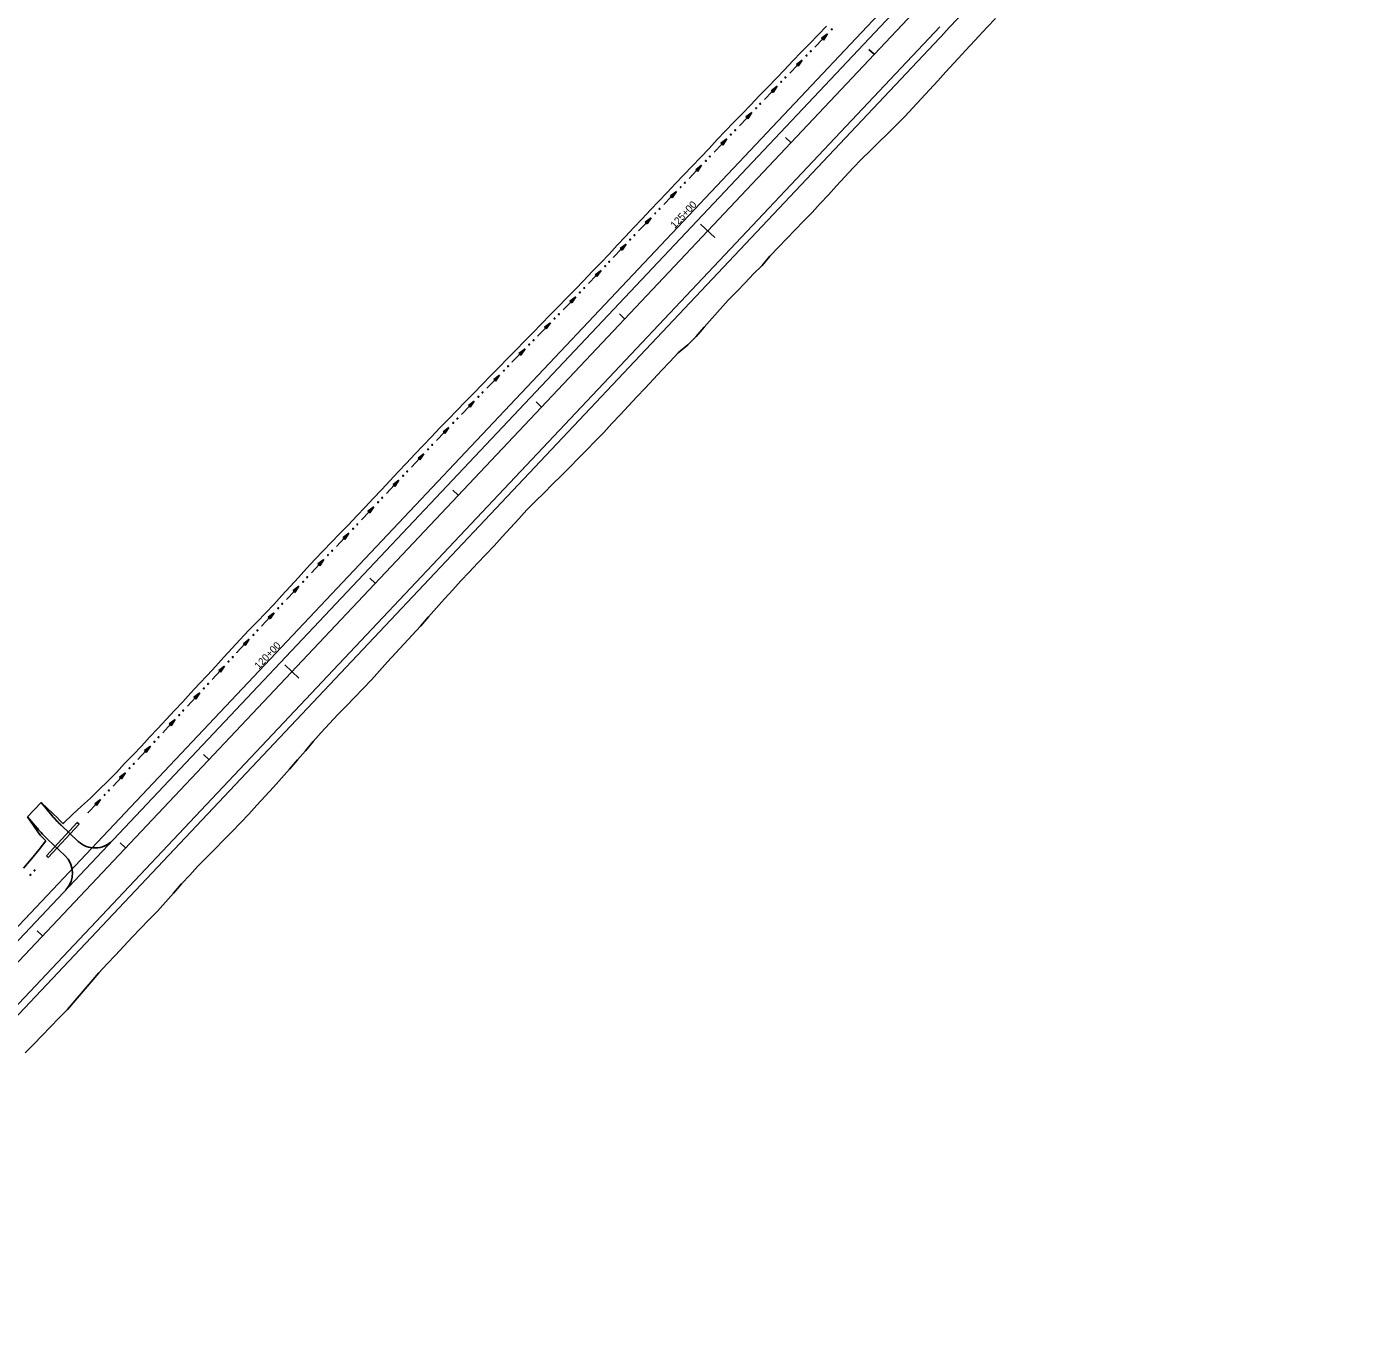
# Model space of a CAD drawing. Extents: x 1375694 to 1433473, y 1931050 to 1967991.
# Drawn here: x 1376795 to 1377906, y 1931932 to 1933018 of the extents above; entities that cross this region are included whole.
import ezdxf

# ---------------------------------------------------------------- set-up
doc = ezdxf.new("R2010")
doc.units = 0
for name, color, linetype in [('62', 7, 'Continuous'), ('R_Drainage', 7, 'Continuous'), ('R_Horz Alg', 7, 'Continuous'), ('R_Horz Alg Annot', 7, 'Continuous'), ('R_Proposed Const Limits', 7, 'Continuous'), ('R_Proposed Road', 7, 'Continuous')]:
    doc.layers.add(name, color=color, linetype=linetype)

msp = doc.modelspace()

# ---------------------------------------------------------------- linework, layer by layer
at = {"layer": '62'}
for p, q in [((1377456, 1933012), (1377451.1, 1933008.4)), ((1377452.7, 1933006.9), (1377456, 1933012)), ((1377451.1, 1933008.4), (1377452.7, 1933006.9)), ((1377435.2, 1932990.4), (1377430.3, 1932986.8)), ((1377431.8, 1932985.3), (1377435.2, 1932990.4)), ((1377430.3, 1932986.8), (1377431.8, 1932985.3)), ((1377414.4, 1932968.7), (1377409.5, 1932965.1)), ((1377409.5, 1932965.1), (1377411, 1932963.7)), ((1377411, 1932963.7), (1377414.4, 1932968.7)), ((1377393.6, 1932947), (1377388.7, 1932943.4)), ((1377388.7, 1932943.4), (1377390.3, 1932941.9)), ((1377390.3, 1932941.9), (1377393.6, 1932947)), ((1377372.9, 1932925.3), (1377368, 1932921.7)), ((1377368, 1932921.7), (1377369.5, 1932920.2)), ((1377369.5, 1932920.2), (1377372.9, 1932925.3)), ((1377352.1, 1932903.6), (1377347.2, 1932899.9)), ((1377347.2, 1932899.9), (1377348.8, 1932898.5)), ((1377348.8, 1932898.5), (1377352.1, 1932903.6)), ((1377331.3, 1932881.9), (1377326.4, 1932878.3)), ((1377326.4, 1932878.3), (1377327.9, 1932876.8)), ((1377327.9, 1932876.8), (1377331.3, 1932881.9)), ((1377310.5, 1932860.3), (1377305.5, 1932856.7)), ((1377305.5, 1932856.7), (1377307.1, 1932855.2)), ((1377307.1, 1932855.2), (1377310.5, 1932860.3)), ((1377289.7, 1932838.6), (1377284.8, 1932834.9)), ((1377284.8, 1932834.9), (1377286.4, 1932833.5)), ((1377286.4, 1932833.5), (1377289.7, 1932838.6)), ((1377269.1, 1932816.8), (1377264.2, 1932813.1)), ((1377264.2, 1932813.1), (1377265.7, 1932811.7)), ((1377265.7, 1932811.7), (1377269.1, 1932816.8)), ((1377248.3, 1932795.1), (1377243.3, 1932791.5)), ((1377243.3, 1932791.5), (1377244.9, 1932790)), ((1377244.9, 1932790), (1377248.3, 1932795.1)), ((1377227.4, 1932773.5), (1377222.4, 1932769.9)), ((1377222.4, 1932769.9), (1377223.9, 1932768.5)), ((1377223.9, 1932768.5), (1377227.4, 1932773.5)), ((1377206.4, 1932752), (1377201.4, 1932748.4)), ((1377201.4, 1932748.4), (1377203, 1932747)), ((1377203, 1932747), (1377206.4, 1932752)), ((1377185.4, 1932730.5), (1377180.5, 1932726.9)), ((1377180.5, 1932726.9), (1377182, 1932725.5)), ((1377182, 1932725.5), (1377185.4, 1932730.5)), ((1377164.5, 1932709), (1377159.6, 1932705.4)), ((1377159.6, 1932705.4), (1377161.1, 1932703.9)), ((1377161.1, 1932703.9), (1377164.5, 1932709)), ((1377143.6, 1932687.3), (1377138.7, 1932683.7)), ((1377140.2, 1932682.3), (1377143.6, 1932687.3)), ((1377138.7, 1932683.7), (1377140.2, 1932682.3)), ((1377123, 1932665.5), (1377118.1, 1932661.9)), ((1377119.6, 1932660.5), (1377123, 1932665.5)), ((1377118.1, 1932661.9), (1377119.6, 1932660.5)), ((1377102.3, 1932643.7), (1377097.5, 1932640.1)), ((1377099, 1932638.6), (1377102.3, 1932643.7)), ((1377097.5, 1932640.1), (1377099, 1932638.6)), ((1377081.7, 1932621.8), (1377076.8, 1932618.2)), ((1377078.4, 1932616.8), (1377081.7, 1932621.8)), ((1377076.8, 1932618.2), (1377078.4, 1932616.8)), ((1377061.1, 1932600), (1377056.2, 1932596.4)), ((1377057.7, 1932594.9), (1377061.1, 1932600)), ((1377056.2, 1932596.4), (1377057.7, 1932594.9)), ((1377040.4, 1932578.2), (1377035.5, 1932574.6)), ((1377037.1, 1932573.1), (1377040.4, 1932578.2)), ((1377035.5, 1932574.6), (1377037.1, 1932573.1)), ((1377019.8, 1932556.3), (1377015, 1932552.7)), ((1377016.5, 1932551.2), (1377019.8, 1932556.3)), ((1377015, 1932552.7), (1377016.5, 1932551.2)), ((1376999.3, 1932534.4), (1376994.4, 1932530.8)), ((1376996, 1932529.3), (1376999.3, 1932534.4)), ((1376994.4, 1932530.8), (1376996, 1932529.3)), ((1376978.8, 1932512.5), (1376974, 1932508.8)), ((1376975.5, 1932507.3), (1376978.8, 1932512.5)), ((1376974, 1932508.8), (1376975.5, 1932507.3)), ((1376958.4, 1932490.4), (1376953.6, 1932486.7)), ((1376955.1, 1932485.3), (1376958.4, 1932490.4)), ((1376953.6, 1932486.7), (1376955.1, 1932485.3)), ((1376938.1, 1932468.3), (1376933.2, 1932464.7)), ((1376934.8, 1932463.2), (1376938.1, 1932468.3)), ((1376933.2, 1932464.7), (1376934.8, 1932463.2)), ((1376917.6, 1932446.3), (1376912.8, 1932442.6)), ((1376912.8, 1932442.6), (1376914.3, 1932441.2)), ((1376914.3, 1932441.2), (1376917.6, 1932446.3)), ((1376897.2, 1932424.3), (1376892.3, 1932420.7)), ((1376892.3, 1932420.7), (1376893.8, 1932419.2)), ((1376893.8, 1932419.2), (1376897.2, 1932424.3)), ((1376876.7, 1932402.4), (1376871.8, 1932398.7)), ((1376871.8, 1932398.7), (1376873.3, 1932397.3)), ((1376873.3, 1932397.3), (1376876.7, 1932402.4)), ((1376856.1, 1932380.4), (1376851.3, 1932376.8)), ((1376851.3, 1932376.8), (1376852.8, 1932375.3)), ((1376852.8, 1932375.3), (1376856.1, 1932380.4))]:
    msp.add_line(p, q, dxfattribs=at)
for points in [[(1377445.7, 1933001.2), (1377451.9, 1933007.7), (1377456, 1933012)], [(1377445.6, 1933001.1), (1377445.7, 1933001.2)], [(1377424.8, 1932979.6), (1377431.1, 1932986.1), (1377435.2, 1932990.4)], [(1377424.8, 1932979.5), (1377424.8, 1932979.6)], [(1377404, 1932957.9), (1377410.3, 1932964.5), (1377414.4, 1932968.7)], [(1377404, 1932957.9), (1377404, 1932957.9)], [(1377383.3, 1932936.2), (1377389.6, 1932942.8), (1377393.6, 1932947)], [(1377383.3, 1932936.1), (1377383.3, 1932936.2)], [(1377362.5, 1932914.4), (1377368.9, 1932921.1), (1377372.9, 1932925.3)], [(1377362.5, 1932914.4), (1377362.5, 1932914.4)], [(1377341.8, 1932892.7), (1377348.1, 1932899.4), (1377352.1, 1932903.6)], [(1377341.8, 1932892.7), (1377341.8, 1932892.7)], [(1377320.9, 1932871.1), (1377327.3, 1932877.7), (1377331.3, 1932881.9)], [(1377320.9, 1932871.1), (1377320.9, 1932871.1)], [(1377300.1, 1932849.5), (1377306.5, 1932856.2), (1377310.5, 1932860.3)], [(1377300.1, 1932849.4), (1377300.1, 1932849.5)], [(1377279.4, 1932827.7), (1377285.8, 1932834.4), (1377289.7, 1932838.6)], [(1377279.4, 1932827.6), (1377279.4, 1932827.7)], [(1377258.7, 1932805.9), (1377265.2, 1932812.7), (1377269.1, 1932816.8)], [(1377258.7, 1932805.9), (1377258.7, 1932805.9)], [(1377237.9, 1932784.3), (1377244.4, 1932791), (1377248.3, 1932795.1)], [(1377237.8, 1932784.3), (1377237.9, 1932784.3)], [(1377216.9, 1932762.8), (1377223.5, 1932769.5), (1377227.4, 1932773.5)], [(1377216.9, 1932762.7), (1377216.9, 1932762.8)], [(1377195.9, 1932741.3), (1377202.5, 1932748), (1377206.4, 1932752)], [(1377195.9, 1932741.2), (1377195.9, 1932741.3)], [(1377175, 1932719.8), (1377181.6, 1932726.5), (1377185.4, 1932730.5)], [(1377174.9, 1932719.7), (1377175, 1932719.8)], [(1377154, 1932698.1), (1377154.1, 1932698.2)], [(1377154.1, 1932698.2), (1377160.7, 1932705), (1377164.5, 1932709)], [(1377133.3, 1932676.5), (1377139.9, 1932683.4), (1377143.6, 1932687.3)], [(1377133.3, 1932676.5), (1377133.3, 1932676.5)], [(1377112.7, 1932654.6), (1377119.3, 1932661.6), (1377123, 1932665.5)], [(1377112.6, 1932654.6), (1377112.7, 1932654.6)], [(1377092.1, 1932632.8), (1377098.7, 1932639.8), (1377102.3, 1932643.7)], [(1377092, 1932632.8), (1377092.1, 1932632.8)], [(1377071.4, 1932610.9), (1377078.1, 1932618), (1377081.7, 1932621.8)], [(1377071.4, 1932610.9), (1377071.4, 1932610.9)], [(1377050.8, 1932589.1), (1377057.5, 1932596.2), (1377061.1, 1932600)], [(1377050.7, 1932589.1), (1377050.8, 1932589.1)], [(1377030.1, 1932567.3), (1377036.8, 1932574.4), (1377040.4, 1932578.2)], [(1377030.1, 1932567.3), (1377030.1, 1932567.3)], [(1377009.6, 1932545.4), (1377016.3, 1932552.5), (1377019.8, 1932556.3)], [(1377009.6, 1932545.4), (1377009.6, 1932545.4)], [(1376989.1, 1932523.5), (1376995.8, 1932530.6), (1376999.3, 1932534.4)], [(1376989.1, 1932523.4), (1376989.1, 1932523.5)], [(1376968.6, 1932501.5), (1376975.3, 1932508.7), (1376978.8, 1932512.5)], [(1376968.6, 1932501.4), (1376968.6, 1932501.5)], [(1376948.3, 1932479.4), (1376955, 1932486.7), (1376958.4, 1932490.4)], [(1376948.2, 1932479.4), (1376948.3, 1932479.4)], [(1376927.9, 1932457.3), (1376934.6, 1932464.6), (1376938.1, 1932468.3)], [(1376927.8, 1932457.3), (1376927.9, 1932457.3)], [(1376907.4, 1932435.3), (1376914.2, 1932442.6), (1376917.6, 1932446.3)], [(1376907.4, 1932435.3), (1376907.4, 1932435.3), (1376907.4, 1932435.3)], [(1376886.9, 1932413.4), (1376886.9, 1932413.4), (1376893.8, 1932420.7), (1376897.2, 1932424.3)], [(1376886.9, 1932413.3), (1376886.9, 1932413.4)], [(1376866.4, 1932391.4), (1376866.4, 1932391.4), (1376873.3, 1932398.8), (1376876.7, 1932402.4)], [(1376866.4, 1932391.4), (1376866.4, 1932391.4)], [(1376845.9, 1932369.5), (1376846, 1932369.5), (1376852.8, 1932376.8), (1376856.1, 1932380.4)], [(1376845.9, 1932369.4), (1376845.9, 1932369.5)]]:
    msp.add_lwpolyline(points, dxfattribs=at)
for centre in [(1377459.5, 1933015.7), (1377438.7, 1932994), (1377442.2, 1932997.6), (1377421.3, 1932976), (1377417.8, 1932972.4), (1377400.5, 1932954.3), (1377397.1, 1932950.7), (1377379.8, 1932932.5), (1377376.3, 1932928.9), (1377359, 1932910.8), (1377355.6, 1932907.2), (1377338.3, 1932889.1), (1377334.8, 1932885.5), (1377317.4, 1932867.5), (1377313.9, 1932863.9), (1377293.1, 1932842.2), (1377296.6, 1932845.9), (1377272.5, 1932820.4), (1377275.9, 1932824), (1377251.7, 1932798.7), (1377255.2, 1932802.3), (1377230.8, 1932777.1), (1377234.3, 1932780.7), (1377209.9, 1932755.6), (1377213.4, 1932759.2), (1377188.9, 1932734.1), (1377192.4, 1932737.7), (1377167.9, 1932712.6), (1377171.4, 1932716.2), (1377147.1, 1932691), (1377150.6, 1932694.6), (1377126.4, 1932669.2), (1377129.8, 1932672.9), (1377105.8, 1932647.4), (1377109.2, 1932651), (1377085.1, 1932625.5), (1377088.6, 1932629.2), (1377064.5, 1932603.7), (1377068, 1932607.3), (1377043.8, 1932581.9), (1377047.3, 1932585.5), (1377023.3, 1932560), (1377026.7, 1932563.7), (1377002.7, 1932538.1), (1377006.1, 1932541.8), (1376982.2, 1932516.1), (1376985.6, 1932519.8), (1376965.2, 1932497.8), (1376961.8, 1932494.1), (1376944.8, 1932475.7), (1376941.4, 1932472), (1376924.4, 1932453.7), (1376921, 1932450), (1376904, 1932431.7), (1376900.6, 1932428), (1376883.5, 1932409.7), (1376880, 1932406.1), (1376863, 1932387.8), (1376859.5, 1932384.1), (1376801.6, 1932321.8), (1376798.2, 1932318.1)]:
    msp.add_circle(centre, 0.375, dxfattribs=at)
at = {"layer": 'R_Drainage'}
for p, q in [((1376836.9, 1932361.4), (1376811.4, 1932333.8)), ((1376812.9, 1932332.4), (1376838.4, 1932360)), ((1376838.4, 1932360), (1376836.9, 1932361.4)), ((1376811.4, 1932333.8), (1376812.9, 1932332.4))]:
    msp.add_line(p, q, dxfattribs=at)
at = {"layer": 'R_Horz Alg'}
msp.add_line((1376510.6, 1931952.4), (1377531.3, 1933034.1), dxfattribs=at)
at = {"layer": 'R_Horz Alg Annot'}
for points in [[(1377490.1, 1932999.2), (1377494.4, 1932995.1)], [(1377421.4, 1932926.4), (1377425.8, 1932922.3)], [(1377351.3, 1932855.1), (1377363, 1932844.1)], [(1377284.2, 1932781), (1377288.5, 1932776.9)], [(1377215.5, 1932708.3), (1377219.9, 1932704.1)], [(1377146.9, 1932635.5), (1377151.3, 1932631.4)], [(1377078.3, 1932562.8), (1377082.6, 1932558.7)], [(1377008.2, 1932491.4), (1377019.8, 1932480.5)], [(1376941, 1932417.3), (1376945.4, 1932413.2)], [(1376872.4, 1932344.6), (1376876.7, 1932340.5)], [(1376803.7, 1932271.9), (1376808.1, 1932267.8)]]:
    msp.add_lwpolyline(points, dxfattribs=at)
at = {"layer": 'R_Proposed Const Limits'}
for p, q in [((1376821, 1932364.5), (1376807, 1932377.9)), ((1376806.3, 1932350.9), (1376795.9, 1932366.1))]:
    msp.add_line(p, q, dxfattribs=at)
for points in [[(1376793.9, 1932171.2), (1376800.9, 1932178.3), (1376807.8, 1932185.5), (1376814.8, 1932192.7), (1376821.8, 1932199.9), (1376828.7, 1932207), (1376835.3, 1932214.6), (1376841.8, 1932222.2), (1376848.3, 1932229.8), (1376854.8, 1932237.4), (1376861.6, 1932244.8), (1376868.5, 1932252), (1376875.3, 1932259.3), (1376882.2, 1932266.6), (1376889.1, 1932273.8), (1376896, 1932281), (1376903, 1932288.2), (1376909.6, 1932295.7), (1376916.3, 1932303.1), (1376923, 1932310.6), (1376929.7, 1932318), (1376936.4, 1932325.4), (1376943.5, 1932332.5), (1376950.6, 1932339.6), (1376957.6, 1932346.7), (1376964.6, 1932353.8), (1376971.6, 1932361), (1376978.5, 1932368.2), (1376985.2, 1932375.6), (1376991.9, 1932383.1), (1376998.7, 1932390.4), (1377005.4, 1932397.8), (1377012.1, 1932405.3), (1377018.6, 1932412.9), (1377025.2, 1932420.4), (1377031.6, 1932428.1), (1377038.2, 1932435.6), (1377044.9, 1932443.1), (1377051.8, 1932450.3), (1377058.8, 1932457.4), (1377065.8, 1932464.6), (1377072.7, 1932471.8), (1377079.6, 1932479.1), (1377086.4, 1932486.4), (1377093, 1932493.9), (1377099.9, 1932501.2), (1377106.6, 1932508.6), (1377113.3, 1932516), (1377120.1, 1932523.4), (1377126.6, 1932530.9), (1377133.4, 1932538.3), (1377140, 1932545.8), (1377146.7, 1932553.2), (1377153.4, 1932560.6), (1377160.4, 1932567.8), (1377167.1, 1932575.2), (1377174, 1932582.4), (1377180.9, 1932589.7), (1377187.6, 1932597.1), (1377194.4, 1932604.5), (1377201.2, 1932611.8), (1377207.9, 1932619.2), (1377214.9, 1932626.4), (1377222.1, 1932633.3), (1377229.1, 1932640.4), (1377236.3, 1932647.4), (1377243.4, 1932654.5), (1377250.3, 1932661.7), (1377257.3, 1932668.8), (1377264.3, 1932676), (1377271.3, 1932683.1), (1377278.1, 1932690.4), (1377285, 1932697.7), (1377291.8, 1932705), (1377298.6, 1932712.4), (1377305.4, 1932719.7), (1377312.3, 1932727), (1377319.1, 1932734.3), (1377326, 1932741.5), (1377332.8, 1932748.8), (1377340.6, 1932755.3), (1377347.6, 1932762.4), (1377354.2, 1932769.9), (1377360.9, 1932777.3), (1377367.5, 1932784.8), (1377374.1, 1932792.3), (1377381.1, 1932799.5), (1377388.1, 1932806.7), (1377395, 1932813.9), (1377402, 1932821), (1377408.4, 1932828.7), (1377415.4, 1932835.9), (1377422.4, 1932843.1), (1377429.3, 1932850.2), (1377436.3, 1932857.4), (1377443.2, 1932864.6), (1377450, 1932872), (1377456.8, 1932879.3), (1377463.5, 1932886.7), (1377470.3, 1932894), (1377477.1, 1932901.4), (1377484.1, 1932908.6), (1377491.3, 1932915.5), (1377498.4, 1932922.5), (1377505.5, 1932929.6), (1377512.6, 1932936.7), (1377519.7, 1932943.7), (1377526.5, 1932951), (1377533.3, 1932958.3), (1377540.1, 1932965.7), (1377546.9, 1932973.1), (1377553.5, 1932980.6), (1377560.3, 1932987.9), (1377567.1, 1932995.2), (1377569.7, 1932997.9), (1377574.1, 1933002.7), (1377580.9, 1933010), (1377587.7, 1933017.4), (1377594.5, 1933024.6)], [(1376825, 1932360.4), (1376825.7, 1932361.1), (1376833, 1932368), (1376840.4, 1932374.8), (1376847.8, 1932381.5), (1376854.9, 1932388.6), (1376862.2, 1932395.5), (1376869.2, 1932402.6), (1376876, 1932409.9), (1376882.9, 1932417.2), (1376889.8, 1932424.4), (1376896.6, 1932431.7), (1376903.5, 1932439), (1376910.3, 1932446.4), (1376917.1, 1932453.7), (1376923.9, 1932461), (1376930.7, 1932468.3), (1376937.5, 1932475.6), (1376944.3, 1932483), (1376951.1, 1932490.3), (1376957.8, 1932497.7), (1376964.6, 1932505.1), (1376971.4, 1932512.4), (1376978.3, 1932519.6), (1376985.3, 1932526.8), (1376992.2, 1932534), (1376999.1, 1932541.3), (1377005.8, 1932548.6), (1377012.6, 1932556), (1377019.4, 1932563.4), (1377026.1, 1932570.8), (1377032.8, 1932578.2), (1377039.7, 1932585.5), (1377046.7, 1932592.6), (1377053.6, 1932599.8), (1377060.6, 1932607), (1377067.5, 1932614.2), (1377074.4, 1932621.5), (1377081.2, 1932628.7), (1377088.1, 1932636), (1377094.9, 1932643.3), (1377101.8, 1932650.6), (1377108.7, 1932657.9), (1377115.5, 1932665.1), (1377122.4, 1932672.4), (1377129.3, 1932679.6), (1377136.2, 1932686.8), (1377143.2, 1932694), (1377150.1, 1932701.2), (1377157.1, 1932708.4), (1377164.1, 1932715.6), (1377171, 1932722.7), (1377178, 1932729.9), (1377185, 1932737.1), (1377192, 1932744.2), (1377199, 1932751.4), (1377206, 1932758.5), (1377213, 1932765.7), (1377220, 1932772.8), (1377226.9, 1932780), (1377233.9, 1932787.1), (1377240.9, 1932794.3), (1377247.9, 1932801.4), (1377254.9, 1932808.6), (1377261.9, 1932815.8), (1377268.8, 1932823), (1377275.7, 1932830.3), (1377282.5, 1932837.6), (1377289.3, 1932844.9), (1377296.2, 1932852.2), (1377303, 1932859.4), (1377309.9, 1932866.7), (1377316.8, 1932873.9), (1377323.7, 1932881.2), (1377330.6, 1932888.4), (1377337.5, 1932895.6), (1377344.4, 1932902.9), (1377351.3, 1932910.1), (1377358.2, 1932917.4), (1377365, 1932924.7), (1377371.9, 1932931.9), (1377378.8, 1932939.1), (1377385.8, 1932946.3), (1377392.7, 1932953.5), (1377399.6, 1932960.8), (1377406.6, 1932968), (1377413.5, 1932975.2), (1377420.4, 1932982.4), (1377427.4, 1932989.6), (1377434.3, 1932996.8), (1377441.3, 1933003.9), (1377448.3, 1933011.1), (1377455.2, 1933018.3)], [(1376792.5, 1932323.7), (1376799.1, 1932331.3), (1376805.4, 1932339.1), (1376811, 1932346.1)]]:
    msp.add_lwpolyline(points, dxfattribs=at)
for radius, start, end in [(90, 223.0567, 226.6795), (110, 222.9733, 226.497)]:
    msp.add_arc((1376886.8, 1932425.9), radius, start, end, dxfattribs=at)
at = {"layer": 'R_Proposed Road'}
for p, q in [((1377553.2, 1933013.6), (1377906.2, 1933391.1)), ((1376496, 1931966.2), (1377516.7, 1933047.9)), ((1376501.8, 1931960.7), (1377522.6, 1933042.4)), ((1376528, 1931936), (1377548.7, 1933017.7)), ((1376532.4, 1931931.8), (1377553.1, 1933013.5)), ((1376807, 1932377.9), (1376795.9, 1932366.1)), ((1376807, 1932377.9), (1376816.2, 1932366.9)), ((1376795.9, 1932366.1), (1376803.9, 1932356.6)), ((1376823.6, 1932359), (1376837.7, 1932345.7)), ((1376812.6, 1932347.4), (1376826.7, 1932334.1))]:
    msp.add_line(p, q, dxfattribs=at)
for centre, radius, start, end in [((1376886.8, 1932425.9), 92, 219.9321, 226.6607), ((1376886.8, 1932425.9), 108, 219.9321, 226.6607), ((1376851.4, 1932360.3), 20, 226.6607, 316.6607), ((1376813, 1932319.5), 20, 316.6607, 46.6607)]:
    msp.add_arc(centre, radius, start, end, dxfattribs=at)

# ---------------------------------------------------------------- texts
at = {"layer": 'R_Horz Alg Annot'}
for s, p in [('125+00', (1377330, 1932851)), ('120+00', (1376986.8, 1932487.3))]:
    msp.add_text(s, height=6, rotation=46.6607, dxfattribs=at).set_placement(p)

doc.saveas('drawing.dxf')
